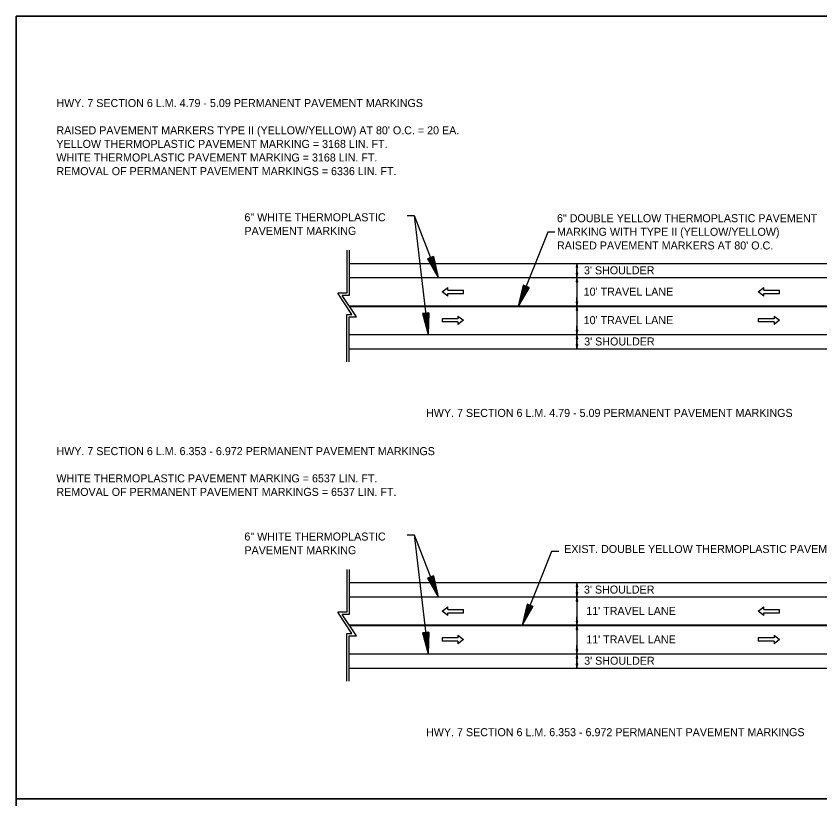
# Model space of a CAD drawing. Extents: x 1372926 to 1373096, y 381240 to 381790.
# Drawn here: x 1372926 to 1373038.9, y 381680.2 to 381790.2 of the extents above; entities that cross this region are included whole.
import ezdxf

# ---------------------------------------------------------------- set-up
doc = ezdxf.new("R2010")
doc.units = 0
for name, color, linetype in [('Default', 7, 'Continuous'), ('DSN_DRFT_Junk-No-Plot', 7, 'Continuous'), ('R_Draft', 7, 'Continuous')]:
    doc.layers.add(name, color=color, linetype=linetype)

msp = doc.modelspace()

# ---------------------------------------------------------------- linework, layer by layer
at = {"layer": 'Default'}
for p, q in [((1372980.91, 381762.15), (1372981.91, 381762.15)), ((1372981.91, 381762.15), (1372985.26, 381753.43)), ((1372981.91, 381762.15), (1372983.86, 381745.43)), ((1373000.66, 381759.79), (1372996.5, 381749.43)), ((1373001.66, 381759.79), (1373000.66, 381759.79)), ((1372972.44, 381757.27), (1372972.44, 381751.26)), ((1372972.78, 381757.27), (1372972.78, 381750.93)), ((1372984.6, 381756.39), (1372983.76, 381756.07)), ((1372983.76, 381756.07), (1372985.26, 381753.43)), ((1372983.83, 381756.1), (1372985.08, 381753.9)), ((1372983.9, 381756.12), (1372984.89, 381754.38)), ((1372983.97, 381756.15), (1372984.71, 381754.85)), ((1372984.05, 381756.18), (1372984.53, 381755.32)), ((1372984.12, 381756.21), (1372984.35, 381755.79)), ((1372984.25, 381756.26), (1372984.35, 381755.79)), ((1372984.32, 381756.28), (1372984.53, 381755.32)), ((1372984.39, 381756.31), (1372984.71, 381754.85)), ((1372984.46, 381756.34), (1372984.89, 381754.38)), ((1372984.53, 381756.36), (1372985.08, 381753.9)), ((1372984.6, 381756.39), (1372985.26, 381753.43)), ((1372985.83, 381751.43), (1372986.61, 381752.03)), ((1372986.61, 381750.83), (1372985.83, 381751.43)), ((1372986.61, 381751.65), (1372986.61, 381752.03)), ((1372986.61, 381751.65), (1372988.81, 381751.65)), ((1372988.81, 381751.2), (1372988.81, 381751.65)), ((1372997.2, 381752.38), (1372996.5, 381749.43)), ((1372998.04, 381752.05), (1372996.5, 381749.43)), ((1372997.27, 381752.35), (1372996.69, 381749.89)), ((1372997.97, 381752.07), (1372996.69, 381749.89)), ((1372997.34, 381752.33), (1372996.88, 381750.37)), ((1372997.9, 381752.1), (1372996.88, 381750.37)), ((1372997.41, 381752.3), (1372997.07, 381750.84)), ((1372997.83, 381752.13), (1372997.07, 381750.84)), ((1372998.04, 381752.05), (1372997.2, 381752.38)), ((1372997.48, 381752.27), (1372997.26, 381751.31)), ((1372997.75, 381752.16), (1372997.26, 381751.31)), ((1372997.55, 381752.24), (1372997.44, 381751.77)), ((1372997.68, 381752.19), (1372997.44, 381751.77)), ((1373030.24, 381751.43), (1373031.02, 381752.03)), ((1373031.02, 381750.83), (1373030.24, 381751.43)), ((1373031.02, 381751.65), (1373031.02, 381752.03)), ((1373031.02, 381751.65), (1373033.23, 381751.65)), ((1373033.23, 381751.2), (1373033.23, 381751.65)), ((1372973.16, 381748.26), (1372971.16, 381751.26)), ((1372972.44, 381751.26), (1372971.16, 381751.26)), ((1372972.78, 381750.93), (1372971.78, 381750.93)), ((1372973.78, 381747.93), (1372971.78, 381750.93)), ((1372986.61, 381751.2), (1372988.81, 381751.2)), ((1372986.61, 381750.83), (1372986.61, 381751.2)), ((1373031.02, 381751.2), (1373033.23, 381751.2)), ((1373031.02, 381750.83), (1373031.02, 381751.2)), ((1372972.44, 381748.26), (1372973.16, 381748.26)), ((1372972.44, 381741.59), (1372972.44, 381748.26)), ((1372983.96, 381748.46), (1372983.06, 381748.36)), ((1372983.06, 381748.36), (1372983.86, 381745.43)), ((1372983.14, 381748.37), (1372983.8, 381745.93)), ((1372983.21, 381748.38), (1372983.74, 381746.44)), ((1372983.29, 381748.38), (1372983.68, 381746.94)), ((1372983.36, 381748.39), (1372983.62, 381747.44)), ((1372983.44, 381748.4), (1372983.56, 381747.94)), ((1372983.58, 381748.42), (1372983.56, 381747.94)), ((1372983.65, 381748.43), (1372983.62, 381747.44)), ((1372983.73, 381748.44), (1372983.68, 381746.94)), ((1372983.81, 381748.44), (1372983.74, 381746.44)), ((1372983.88, 381748.45), (1372983.8, 381745.93)), ((1372983.96, 381748.46), (1372983.86, 381745.43)), ((1372988.04, 381748.03), (1372988.04, 381747.65)), ((1372988.04, 381748.03), (1372988.81, 381747.43)), ((1373032.45, 381748.03), (1373032.45, 381747.65)), ((1373032.45, 381748.03), (1373033.23, 381747.43)), ((1372972.78, 381741.59), (1372972.78, 381747.93)), ((1372972.78, 381747.93), (1372973.78, 381747.93)), ((1372988.04, 381747.65), (1372985.83, 381747.65)), ((1372985.83, 381747.65), (1372985.83, 381747.2)), ((1372988.04, 381747.2), (1372985.83, 381747.2)), ((1372988.81, 381747.43), (1372988.04, 381746.83)), ((1372988.04, 381747.2), (1372988.04, 381746.83)), ((1373032.45, 381747.65), (1373030.24, 381747.65)), ((1373030.24, 381747.65), (1373030.24, 381747.2)), ((1373032.45, 381747.2), (1373030.24, 381747.2)), ((1373033.23, 381747.43), (1373032.45, 381746.83)), ((1373032.45, 381747.2), (1373032.45, 381746.83)), ((1372980.91, 381717.29), (1372981.91, 381717.29)), ((1372981.91, 381717.29), (1372985.26, 381708.57)), ((1372981.91, 381717.29), (1372983.86, 381700.57)), ((1373001.21, 381714.96), (1372997.05, 381704.61)), ((1373002.21, 381714.96), (1373001.21, 381714.96)), ((1372972.44, 381712.41), (1372972.44, 381706.4)), ((1372972.78, 381712.41), (1372972.78, 381706.07)), ((1372984.6, 381711.53), (1372983.76, 381711.21)), ((1372983.76, 381711.21), (1372985.26, 381708.57)), ((1372983.83, 381711.24), (1372985.08, 381709.04)), ((1372983.9, 381711.26), (1372984.89, 381709.52)), ((1372983.97, 381711.29), (1372984.71, 381709.99)), ((1372984.05, 381711.32), (1372984.53, 381710.46)), ((1372984.12, 381711.35), (1372984.35, 381710.93)), ((1372984.25, 381711.4), (1372984.35, 381710.93)), ((1372984.32, 381711.42), (1372984.53, 381710.46)), ((1372984.39, 381711.45), (1372984.71, 381709.99)), ((1372984.46, 381711.48), (1372984.89, 381709.52)), ((1372984.53, 381711.5), (1372985.08, 381709.04)), ((1372984.6, 381711.53), (1372985.26, 381708.57)), ((1372997.75, 381707.56), (1372997.05, 381704.61)), ((1372997.82, 381707.53), (1372997.24, 381705.07)), ((1372997.89, 381707.5), (1372997.43, 381705.55)), ((1372997.96, 381707.47), (1372997.62, 381706.01)), ((1372998.59, 381707.22), (1372997.75, 381707.56)), ((1372998.04, 381707.44), (1372997.81, 381706.49)), ((1372998.31, 381707.34), (1372997.81, 381706.49)), ((1372998.11, 381707.42), (1372998, 381706.95)), ((1372998.24, 381707.36), (1372998, 381706.95)), ((1372973.16, 381703.4), (1372971.16, 381706.4)), ((1372972.44, 381706.4), (1372971.16, 381706.4)), ((1372985.83, 381706.57), (1372986.61, 381707.17)), ((1372986.61, 381705.97), (1372985.83, 381706.57)), ((1372986.61, 381706.79), (1372986.61, 381707.17)), ((1372986.61, 381706.79), (1372988.81, 381706.79)), ((1372986.61, 381706.34), (1372988.81, 381706.34)), ((1372986.61, 381705.97), (1372986.61, 381706.34)), ((1372988.81, 381706.34), (1372988.81, 381706.79)), ((1372998.59, 381707.22), (1372997.05, 381704.61)), ((1372998.52, 381707.25), (1372997.24, 381705.07)), ((1372998.45, 381707.28), (1372997.43, 381705.55)), ((1372998.38, 381707.31), (1372997.62, 381706.01)), ((1373030.24, 381706.57), (1373031.02, 381707.17)), ((1373031.02, 381705.97), (1373030.24, 381706.57)), ((1373031.02, 381706.79), (1373031.02, 381707.17)), ((1373031.02, 381706.79), (1373033.23, 381706.79)), ((1373031.02, 381706.34), (1373033.23, 381706.34)), ((1373031.02, 381705.97), (1373031.02, 381706.34)), ((1373033.23, 381706.34), (1373033.23, 381706.79)), ((1372972.78, 381706.07), (1372971.78, 381706.07)), ((1372973.78, 381703.07), (1372971.78, 381706.07)), ((1372972.44, 381703.4), (1372973.16, 381703.4)), ((1372972.44, 381696.73), (1372972.44, 381703.4)), ((1372972.78, 381696.73), (1372972.78, 381703.07)), ((1372972.78, 381703.07), (1372973.78, 381703.07)), ((1372983.96, 381703.6), (1372983.06, 381703.5)), ((1372983.06, 381703.5), (1372983.86, 381700.57)), ((1372983.14, 381703.51), (1372983.8, 381701.07)), ((1372983.21, 381703.52), (1372983.74, 381701.58)), ((1372983.29, 381703.52), (1372983.68, 381702.08)), ((1372983.36, 381703.53), (1372983.62, 381702.58)), ((1372983.44, 381703.54), (1372983.56, 381703.08)), ((1372983.58, 381703.56), (1372983.56, 381703.08)), ((1372983.65, 381703.57), (1372983.62, 381702.58)), ((1372983.73, 381703.58), (1372983.68, 381702.08)), ((1372983.81, 381703.58), (1372983.74, 381701.58)), ((1372983.88, 381703.59), (1372983.8, 381701.07)), ((1372983.96, 381703.6), (1372983.86, 381700.57)), ((1372988.04, 381703.17), (1372988.04, 381702.79)), ((1372988.04, 381703.17), (1372988.81, 381702.57)), ((1373032.45, 381703.17), (1373032.45, 381702.79)), ((1373032.45, 381703.17), (1373033.23, 381702.57)), ((1372988.04, 381702.79), (1372985.83, 381702.79)), ((1372985.83, 381702.79), (1372985.83, 381702.34)), ((1372988.04, 381702.34), (1372985.83, 381702.34)), ((1372988.81, 381702.57), (1372988.04, 381701.97)), ((1372988.04, 381702.34), (1372988.04, 381701.97)), ((1373032.45, 381702.79), (1373030.24, 381702.79)), ((1373030.24, 381702.79), (1373030.24, 381702.34)), ((1373032.45, 381702.34), (1373030.24, 381702.34)), ((1373033.23, 381702.57), (1373032.45, 381701.97)), ((1373032.45, 381702.34), (1373032.45, 381701.97))]:
    msp.add_line(p, q, dxfattribs=at)
for points in [[(1372925.97, 381790.17), (1372925.97, 381680.17), (1373095.97, 381680.17), (1373095.97, 381790.17)], [(1372925.97, 381680.17), (1372925.97, 381570.17), (1373095.97, 381570.17), (1373095.97, 381680.17)]]:
    msp.add_lwpolyline(points, close=True, dxfattribs=at)
at = {"layer": 'DSN_DRFT_Junk-No-Plot'}
for p, q in [((1373004.76, 381755.43), (1373004.76, 381743.43)), ((1373004.76, 381710.57), (1373004.76, 381698.57))]:
    msp.add_line(p, q, dxfattribs=at)
for points in [[(1372925.97, 381790.17), (1373095.97, 381790.17), (1373095.97, 381680.17), (1372925.97, 381680.17)], [(1372925.97, 381790.17), (1372925.97, 381680.17), (1373095.97, 381680.17), (1373095.97, 381790.17)], [(1372925.97, 381680.17), (1373095.97, 381680.17), (1373095.97, 381570.17), (1372925.97, 381570.17)], [(1372925.97, 381680.17), (1372925.97, 381570.17), (1373095.97, 381570.17), (1373095.97, 381680.17)]]:
    msp.add_lwpolyline(points, close=True, dxfattribs=at)
for points in [[(1373004.76, 381755.43), (1373004.64, 381754.83), (1373004.88, 381754.83), (1373004.76, 381755.43), (1373004.76, 381754.23)], [(1373004.76, 381753.43), (1373004.88, 381754.03), (1373004.64, 381754.03), (1373004.76, 381753.43), (1373004.76, 381754.63)], [(1373004.76, 381753.43), (1373004.64, 381752.83), (1373004.88, 381752.83), (1373004.76, 381753.43), (1373004.76, 381752.23)], [(1373004.76, 381749.43), (1373004.88, 381750.03), (1373004.64, 381750.03), (1373004.76, 381749.43), (1373004.76, 381750.63)], [(1373004.76, 381749.43), (1373004.64, 381748.83), (1373004.88, 381748.83), (1373004.76, 381749.43), (1373004.76, 381748.23)], [(1373004.76, 381745.43), (1373004.88, 381746.03), (1373004.64, 381746.03), (1373004.76, 381745.43), (1373004.76, 381746.63)], [(1373004.76, 381745.43), (1373004.64, 381744.83), (1373004.88, 381744.83), (1373004.76, 381745.43), (1373004.76, 381744.23)], [(1373004.76, 381743.43), (1373004.88, 381744.03), (1373004.64, 381744.03), (1373004.76, 381743.43), (1373004.76, 381744.63)], [(1373004.76, 381710.57), (1373004.64, 381709.97), (1373004.88, 381709.97), (1373004.76, 381710.57), (1373004.76, 381709.37)], [(1373004.76, 381708.57), (1373004.88, 381709.17), (1373004.64, 381709.17), (1373004.76, 381708.57), (1373004.76, 381709.77)], [(1373004.76, 381708.57), (1373004.64, 381707.97), (1373004.88, 381707.97), (1373004.76, 381708.57), (1373004.76, 381707.37)], [(1373004.76, 381704.57), (1373004.88, 381705.17), (1373004.64, 381705.17), (1373004.76, 381704.57), (1373004.76, 381705.77)], [(1373004.76, 381704.57), (1373004.64, 381703.97), (1373004.88, 381703.97), (1373004.76, 381704.57), (1373004.76, 381703.37)], [(1373004.76, 381700.57), (1373004.88, 381701.17), (1373004.64, 381701.17), (1373004.76, 381700.57), (1373004.76, 381701.77)], [(1373004.76, 381700.57), (1373004.64, 381699.97), (1373004.88, 381699.97), (1373004.76, 381700.57), (1373004.76, 381699.37)], [(1373004.76, 381698.57), (1373004.88, 381699.17), (1373004.64, 381699.17), (1373004.76, 381698.57), (1373004.76, 381699.77)]]:
    msp.add_lwpolyline(points, dxfattribs=at)
at = {"layer": 'R_Draft'}
for p, q in [((1372972.78, 381755.43), (1373049.17, 381755.43)), ((1372972.78, 381753.43), (1373049.17, 381753.43)), ((1372972.74, 381749.48), (1373049.14, 381749.48)), ((1372972.81, 381749.38), (1373049.2, 381749.38)), ((1372972.78, 381745.43), (1373049.17, 381745.43)), ((1372972.78, 381743.43), (1373049.17, 381743.43)), ((1372972.78, 381710.57), (1373049.17, 381710.57)), ((1372972.78, 381708.57), (1373049.17, 381708.57)), ((1372972.74, 381704.62), (1373049.14, 381704.62)), ((1372972.81, 381704.52), (1373049.2, 381704.52)), ((1372972.78, 381700.57), (1373049.17, 381700.57)), ((1372972.78, 381698.57), (1373049.17, 381698.57))]:
    msp.add_line(p, q, dxfattribs=at)

# ---------------------------------------------------------------- texts
at = {"layer": 'Default'}
for s, p in [('HWY. 7 SECTION 6 L.M. 4.79 - 5.09 PERMANENT PAVEMENT MARKINGS', (1372931.64, 381777.39)), ("RAISED PAVEMENT MARKERS TYPE II (YELLOW/YELLOW) AT 80' O.C. = 20 EA.", (1372931.64, 381773.56)), ('YELLOW THERMOPLASTIC PAVEMENT MARKING = 3168 LIN. FT.', (1372931.64, 381771.65)), ('WHITE THERMOPLASTIC PAVEMENT MARKING = 3168 LIN. FT.', (1372931.64, 381769.74)), ('REMOVAL OF PERMANENT PAVEMENT MARKINGS = 6336 LIN. FT.', (1372931.64, 381767.82)), ('6" WHITE THERMOPLASTIC', (1372958.05, 381761.34)), ('6" DOUBLE YELLOW THERMOPLASTIC PAVEMENT', (1373001.96, 381761.21)), ('PAVEMENT MARKING', (1372958.05, 381759.43)), ('MARKING WITH TYPE II (YELLOW/YELLOW)', (1373001.96, 381759.3)), ("RAISED PAVEMENT MARKERS AT 80' O.C.", (1373001.96, 381757.38)), ('HWY. 7 SECTION 6 L.M. 6.353 - 6.972 PERMANENT PAVEMENT MARKINGS', (1372931.64, 381728.48)), ('WHITE THERMOPLASTIC PAVEMENT MARKING = 6537 LIN. FT.', (1372931.64, 381724.66)), ('REMOVAL OF PERMANENT PAVEMENT MARKINGS = 6537 LIN. FT.', (1372931.64, 381722.75)), ('6" WHITE THERMOPLASTIC', (1372958.05, 381716.48)), ('PAVEMENT MARKING', (1372958.05, 381714.56)), ('EXIST. DOUBLE YELLOW THERMOPLASTIC PAVEMENT MARKING (RETAIN)', (1373002.97, 381714.73))]:
    msp.add_text(s, height=1.125, dxfattribs=at).set_placement(p)
at = {"layer": 'R_Draft'}
for s, p in [("3' SHOULDER", (1373005.75, 381753.89)), ("10' TRAVEL LANE", (1373005.71, 381750.89)), ("10' TRAVEL LANE", (1373005.71, 381746.89)), ("3' SHOULDER", (1373005.78, 381743.89)), ('HWY. 7 SECTION 6 L.M. 4.79 - 5.09 PERMANENT PAVEMENT MARKINGS', (1372983.57, 381733.85)), ("3' SHOULDER", (1373005.75, 381709.03)), ("11' TRAVEL LANE", (1373006.07, 381706.03)), ("11' TRAVEL LANE", (1373006.07, 381702.03)), ("3' SHOULDER", (1373005.78, 381699.03)), ('HWY. 7 SECTION 6 L.M. 6.353 - 6.972 PERMANENT PAVEMENT MARKINGS', (1372983.57, 381688.99))]:
    msp.add_text(s, height=1.125, dxfattribs=at).set_placement(p)

doc.saveas('drawing.dxf')
